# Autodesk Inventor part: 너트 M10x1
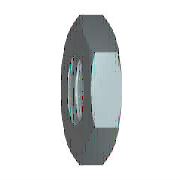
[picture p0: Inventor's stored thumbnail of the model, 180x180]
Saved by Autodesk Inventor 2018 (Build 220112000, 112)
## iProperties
Created: 2012-02
Part Number: 너트 M10x1
Material: 강철, 연강
Description: 6각 가는 너트 - 이중 모따기(부품 등급 A) - 정밀 나사산
Document SubType Name: Modeling
Standard: JIS B 1181
Designer: mduedu
Standards Organization: JIS
Language: ko-KR
Size Designation: M10x1
Categories: <MemberInstance><Categories><Category DisplayName="조임쇠" InternalName="e4da775c-781d-43d5-af7c-5136215cf5a6" Mnemonic="FSTN"><Category DisplayName="너트" InternalN
Density: 7.85 g/cm^3
Appearance: 강철
Mass: 6.12359 g
Surface Area: 6.99154 cm^2
Volume: 0.780075 cm^3
IsCustomPart: 1
Author: mduedu
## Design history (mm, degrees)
node "MSC_A1"
node "MSC_PT1"
node "MSC_PT2"
node "MSC_PF1"
body "Solid1"
sketch "스케치1"
  geometry: L1 (8, 4.619)-(8, -4.619); L2 (8, -4.619)-(0, -9.238); L3 (0, -9.238)-(-8, -4.619); L4 (-8, -4.619)-(-8, 4.619); L5 (-8, 4.619)-(0, 9.238); L6 (0, 9.238)-(8, 4.619); C1 r 8 at (0, 0); 2 further points
  constraints: 12 end point, 2 coincident, 1 centre point, 1 tangent, 1 vertical, 11 other
  dimensions: "d0" = 16 diameter of C1 (= ParS)
extrude "돌출1" new body sketch "스케치1" distance "d1" = 5 (= M); taper "d2" = 0 deg
sketch "스케치2"
  geometry: L1 (-8, 4.619)-(0, 9.238) reference; L2 (0, -9.238)-(-8, -4.619) reference; L3 (-8, 4.619)-(8, -4.619); L4 (-8, -4.619)-(8, 4.619); 1 further point
  constraints: 4 end point, 2 midpoint, 2 parallel
hole "구멍1" sketch "스케치2" diameter "d3" = 8.91747; stored, may be unused: countersink angle "d7" = 90 deg, drill point angle "d9" = 118 deg; dims "d4" = 6, "d5" = 4, "d6" = 2, "d8" = 8
chamfer "모따기1" distance "d10" = 0.5 (= 0.5 x PTC); stored, may be unused: second distance "d11" = 2, angle "d12" = 45 deg
revolve "회전1" stored, may be unused: angle "d15" = 90 deg
sketch "스케치3"
  geometry: L1 (-9.238, 5)-(-9.238, 4.285); L2 (-9.238, 4.285)-(-8, 5); L3 (-8, 5)-(-9.238, 5); L4 (-9.238, 0.715)-(-9.238, 0); L5 (-9.238, 0)-(-8, 0); L6 (-8, 0)-(-9.238, 0.715); L7 (0, 6)-(0, -1) reference; L8 (-4.619, 5)-(-9.238, 5) reference; L9 (-4.619, 0)-(-9.238, 0) reference; L10 (-9.238, 0)-(-9.238, 5) reference
  constraints: 12 end point, 4 collinear, 3 perpendicular, 2 equal length, 1 vertical
  dimensions: "d13" = 30 deg angle of L2 L3; "d14" = 8 distance from line of L2.end L7 (= 0.5 x ParS)
other parameters: "ParS" = 16 [user parameter; used in 2 equation terms], "M" = 5 [user parameter; used in 1 equation term], "PTC" = 1 [user parameter; used in 1 equation term], "d17" = 0, "d18" = 0, "d19" = 0, "d20" = 0, "d21" = 0, "d22" = 0, "d23" = 0
